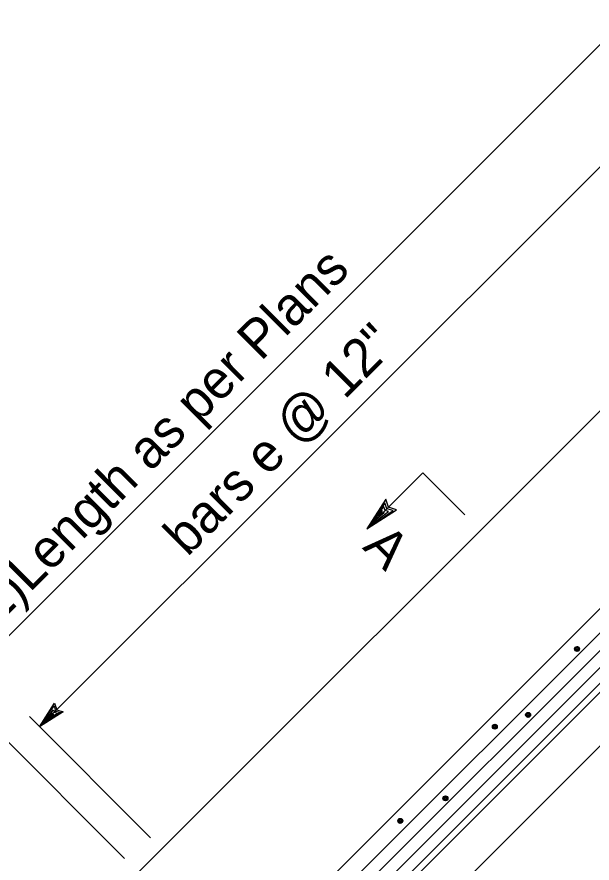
# Model space of a CAD drawing. Extents: x -0.08 to 2.83, y -0.03 to 1.92.
# Drawn here: x 0.22 to 0.4158, y 1.327 to 1.6151 of the extents above; entities that cross this region are included whole.
import ezdxf

# ---------------------------------------------------------------- set-up
doc = ezdxf.new("R2010")
doc.units = 0
for name, color, linetype in [('50', 7, 'Continuous'), ('51', 7, 'Continuous'), ('55', 7, 'Continuous'), ('57', 7, 'Continuous')]:
    doc.layers.add(name, color=color, linetype=linetype)

msp = doc.modelspace()

# ---------------------------------------------------------------- linework, layer by layer
at = {"layer": '50'}
for p, q in [((0.26143, 1.32383), (0.52603, 1.58845)), ((0.29508, 1.29018), (0.52603, 1.52115)), ((0.30931, 1.27596), (0.54531, 1.51199)), ((0.31847, 1.2668), (0.55291, 1.50128)), ((0.30513, 1.28013), (0.51959, 1.49462))]:
    msp.add_line(p, q, dxfattribs=at)
at = {"layer": '51'}
for p, q in [((0.5075, 1.49439), (0.30176, 1.28865)), ((0.51042, 1.4913), (0.30496, 1.28583))]:
    msp.add_line(p, q, dxfattribs=at)
for points in [[(0.41021, 1.40049), (0.41052, 1.40064), (0.41084, 1.40065), (0.41114, 1.40053), (0.41135, 1.40034), (0.41146, 1.40014), (0.41148, 1.39991), (0.41143, 1.39967), (0.41135, 1.39946), (0.41118, 1.39926), (0.41095, 1.39912), (0.41073, 1.39908), (0.41047, 1.39912), (0.41024, 1.39924), (0.41002, 1.39946), (0.40995, 1.39971), (0.40992, 1.39994), (0.40996, 1.40013), (0.41006, 1.40031), (0.41019, 1.40043), (0.41038, 1.40052), (0.41057, 1.40059), (0.4108, 1.4006), (0.41096, 1.40057), (0.4111, 1.40052), (0.41119, 1.40042), (0.41133, 1.40029), (0.41139, 1.40013), (0.41141, 1.39997), (0.41142, 1.39982), (0.41138, 1.39964), (0.41129, 1.39948), (0.41117, 1.39933), (0.41104, 1.39924), (0.41086, 1.39914), (0.41074, 1.39913), (0.41057, 1.39915), (0.41043, 1.39919), (0.41031, 1.39927), (0.41017, 1.39937), (0.41004, 1.39956), (0.40999, 1.39975), (0.40997, 1.39994), (0.41004, 1.40018), (0.41016, 1.40034), (0.41034, 1.40044), (0.41052, 1.40052), (0.41073, 1.40055), (0.41089, 1.40054), (0.41103, 1.40048), (0.41119, 1.40036), (0.41129, 1.40021), (0.41133, 1.40006), (0.41135, 1.39987), (0.41131, 1.39967), (0.41121, 1.3995), (0.41107, 1.39935), (0.41095, 1.39925), (0.41073, 1.39919), (0.41056, 1.39921), (0.4104, 1.39928), (0.41023, 1.39941), (0.41011, 1.39959), (0.41004, 1.39977), (0.41004, 1.39994), (0.41008, 1.40009), (0.41016, 1.40022), (0.41028, 1.40035), (0.41041, 1.4004), (0.41055, 1.40045), (0.41068, 1.40048), (0.41087, 1.40048), (0.41102, 1.40043), (0.41115, 1.40032), (0.41123, 1.40019), (0.41126, 1.39996), (0.41123, 1.39976), (0.41116, 1.39958), (0.41102, 1.39941), (0.4109, 1.39933), (0.4108, 1.39929), (0.41061, 1.39926), (0.4105, 1.3993), (0.41031, 1.3994), (0.41019, 1.39957), (0.41012, 1.39976), (0.4101, 1.39994), (0.41015, 1.40011), (0.41023, 1.40024), (0.41039, 1.40034), (0.41059, 1.40039), (0.41077, 1.40043), (0.41092, 1.40043), (0.41107, 1.40035), (0.4111, 1.40028), (0.41117, 1.40018), (0.41118, 1.40006), (0.41118, 1.39988), (0.41117, 1.39977), (0.41114, 1.39967), (0.4111, 1.39958)], [(0.4111, 1.39958), (0.41089, 1.39944), (0.41076, 1.39933), (0.41064, 1.39933), (0.4105, 1.39937), (0.41037, 1.39946), (0.41025, 1.39956), (0.41019, 1.39972), (0.41017, 1.39987), (0.41017, 1.4), (0.41022, 1.40013), (0.41039, 1.40026), (0.41056, 1.40032), (0.41071, 1.40035), (0.41088, 1.40038), (0.41102, 1.40032), (0.41108, 1.40016), (0.41109, 1.40008), (0.4111, 1.39994), (0.41109, 1.39983), (0.41106, 1.39972), (0.41101, 1.39963), (0.41095, 1.39955), (0.41087, 1.39951), (0.41074, 1.39943), (0.41066, 1.3994), (0.41061, 1.3994), (0.4105, 1.39942), (0.41045, 1.39946), (0.41039, 1.3995), (0.41032, 1.39957), (0.41029, 1.39962), (0.41024, 1.39969), (0.41023, 1.39978), (0.41026, 1.40002), (0.41031, 1.40011), (0.4104, 1.4002), (0.41052, 1.40025), (0.4106, 1.40027), (0.41071, 1.40031), (0.4108, 1.40031), (0.41089, 1.4003), (0.41097, 1.40026), (0.41103, 1.40013), (0.41104, 1.40009), (0.41104, 1.4), (0.41103, 1.39991), (0.41102, 1.39983), (0.41099, 1.39976), (0.41098, 1.3997), (0.41094, 1.39963), (0.41092, 1.3996), (0.41084, 1.39956), (0.4108, 1.39954), (0.41074, 1.39951), (0.41066, 1.39949), (0.41059, 1.39948), (0.41053, 1.39949), (0.41045, 1.39954), (0.41039, 1.3996), (0.41034, 1.39966), (0.41032, 1.39972), (0.41031, 1.39982), (0.41031, 1.39991), (0.41034, 1.39998), (0.41037, 1.40004), (0.41039, 1.40011), (0.41047, 1.40013), (0.41055, 1.40016), (0.41064, 1.4002), (0.41072, 1.40022), (0.4108, 1.40022), (0.41086, 1.4002), (0.41092, 1.40013), (0.41096, 1.40004), (0.41097, 1.4), (0.41095, 1.3999), (0.41094, 1.39983), (0.41093, 1.39979), (0.41091, 1.39974), (0.41087, 1.39969), (0.41082, 1.39963), (0.4108, 1.39961), (0.41076, 1.39959), (0.4107, 1.39958), (0.41065, 1.39958), (0.41062, 1.39958), (0.41059, 1.39957), (0.41055, 1.39957), (0.41051, 1.39959), (0.41047, 1.39963), (0.41043, 1.39968), (0.4104, 1.39972), (0.41038, 1.39977), (0.41037, 1.39984), (0.41037, 1.39989), (0.41038, 1.39994), (0.41042, 1.39998), (0.41044, 1.40004), (0.41047, 1.40008), (0.41053, 1.40009)], [(0.39353, 1.37802), (0.39384, 1.37818), (0.39416, 1.37818), (0.39446, 1.37807), (0.39466, 1.37788), (0.39478, 1.37768), (0.3948, 1.37744), (0.39477, 1.3772), (0.39467, 1.377), (0.3945, 1.3768), (0.39428, 1.37666), (0.39406, 1.37662), (0.39379, 1.37666), (0.39356, 1.37678), (0.39335, 1.37699), (0.39327, 1.37725), (0.39325, 1.37748), (0.39329, 1.37766), (0.39338, 1.37785), (0.39352, 1.37797), (0.3937, 1.37806), (0.3939, 1.37813), (0.39412, 1.37814), (0.39429, 1.3781), (0.39442, 1.37806), (0.39453, 1.37796), (0.39465, 1.37783), (0.39471, 1.37767), (0.39473, 1.37751), (0.39474, 1.37736), (0.39471, 1.37719), (0.39462, 1.37702), (0.39449, 1.37688), (0.39437, 1.37678), (0.39419, 1.37668), (0.39407, 1.37667), (0.39391, 1.3767), (0.39376, 1.37672), (0.39363, 1.3768), (0.39349, 1.37692), (0.39337, 1.37709), (0.39331, 1.3773), (0.3933, 1.37748), (0.39337, 1.37771), (0.39348, 1.37787), (0.39366, 1.37798), (0.39385, 1.37806), (0.39406, 1.37808), (0.39421, 1.37808), (0.39437, 1.37801), (0.39452, 1.3779), (0.39461, 1.37775), (0.39465, 1.3776), (0.39466, 1.37741), (0.39462, 1.3772), (0.39453, 1.37704), (0.3944, 1.37688), (0.39427, 1.37679), (0.39406, 1.37672), (0.39388, 1.37675), (0.39372, 1.37682), (0.39355, 1.37695), (0.39343, 1.37713), (0.39337, 1.37731), (0.39337, 1.37747), (0.3934, 1.37764), (0.39348, 1.37776), (0.3936, 1.37788), (0.39374, 1.37793), (0.39387, 1.37798), (0.39401, 1.37801), (0.3942, 1.37801), (0.39435, 1.37797), (0.39447, 1.37785), (0.39455, 1.37773), (0.39458, 1.37749), (0.39456, 1.3773), (0.39449, 1.37711), (0.39435, 1.37695), (0.39422, 1.37687), (0.39413, 1.37682), (0.39394, 1.3768), (0.39382, 1.37684), (0.39364, 1.37693), (0.39352, 1.37711), (0.39344, 1.3773), (0.39343, 1.37747), (0.39347, 1.37764), (0.39356, 1.37777), (0.39371, 1.37787), (0.39391, 1.37793), (0.39409, 1.37797), (0.39424, 1.37797), (0.39439, 1.37788), (0.39442, 1.37782), (0.39449, 1.37773), (0.39451, 1.3776), (0.39451, 1.37742), (0.39449, 1.37731), (0.39446, 1.37721), (0.39442, 1.37711)], [(0.39442, 1.37711), (0.39421, 1.37698), (0.39408, 1.37687), (0.39396, 1.37688), (0.39382, 1.3769), (0.3937, 1.37699), (0.39358, 1.3771), (0.39351, 1.37725), (0.39349, 1.3774), (0.39351, 1.37754), (0.39355, 1.37767), (0.39371, 1.37779), (0.39388, 1.37786), (0.39403, 1.37788), (0.3942, 1.37792), (0.39434, 1.37785), (0.3944, 1.37769), (0.39441, 1.37761), (0.39442, 1.37747), (0.39441, 1.37737), (0.39439, 1.37725), (0.39433, 1.37717), (0.39427, 1.37709), (0.3942, 1.37704), (0.39406, 1.37697), (0.39399, 1.37693), (0.39394, 1.37694), (0.39382, 1.37697), (0.39377, 1.37699), (0.39371, 1.37704), (0.39365, 1.37711), (0.39361, 1.37715), (0.39356, 1.37722), (0.39356, 1.37731), (0.39359, 1.37755), (0.39363, 1.37765), (0.39372, 1.37774), (0.39384, 1.37779), (0.39392, 1.37781), (0.39403, 1.37784), (0.39412, 1.37784), (0.39421, 1.37784), (0.3943, 1.3778), (0.39436, 1.37767), (0.39437, 1.37762), (0.39437, 1.37754), (0.39437, 1.37745), (0.39434, 1.37737), (0.39432, 1.3773), (0.3943, 1.37723), (0.39427, 1.37717), (0.39424, 1.37714), (0.39416, 1.3771), (0.39412, 1.37707), (0.39407, 1.37704), (0.39399, 1.37702), (0.39391, 1.37702), (0.39386, 1.37703), (0.39377, 1.37709), (0.39371, 1.37714), (0.39366, 1.3772), (0.39365, 1.37726), (0.39363, 1.37735), (0.39363, 1.37744), (0.39366, 1.37751), (0.39369, 1.37757), (0.39371, 1.37764), (0.39379, 1.37766), (0.39387, 1.37769), (0.39397, 1.37774), (0.39404, 1.37776), (0.39412, 1.37776), (0.39419, 1.37774), (0.39424, 1.37766), (0.39429, 1.37757), (0.39429, 1.37754), (0.39428, 1.37744), (0.39427, 1.37737), (0.39425, 1.37733), (0.39423, 1.37728), (0.3942, 1.37722), (0.39415, 1.37717), (0.39412, 1.37714), (0.39408, 1.37713), (0.39403, 1.37712), (0.39397, 1.37712), (0.39394, 1.37711), (0.39391, 1.37711), (0.39387, 1.37711), (0.39384, 1.37713), (0.3938, 1.37716), (0.39376, 1.37722), (0.39372, 1.37726), (0.39371, 1.37731), (0.3937, 1.37737), (0.39369, 1.37743), (0.3937, 1.37747), (0.39374, 1.37751), (0.39376, 1.37757), (0.39379, 1.37761), (0.39386, 1.37764)], [(0.38222, 1.37404), (0.38252, 1.37418), (0.38285, 1.37419), (0.38315, 1.37408), (0.38336, 1.37389), (0.38347, 1.37368), (0.3835, 1.37345), (0.38346, 1.3732), (0.38336, 1.37301), (0.38318, 1.3728), (0.38296, 1.37266), (0.38274, 1.37263), (0.38248, 1.37267), (0.38226, 1.37279), (0.38204, 1.373), (0.38195, 1.37326), (0.38194, 1.37348), (0.38198, 1.37367), (0.38207, 1.37386), (0.38221, 1.37398), (0.38239, 1.37407), (0.38258, 1.37413), (0.38281, 1.37415), (0.38297, 1.37411), (0.38311, 1.37406), (0.38321, 1.37397), (0.38334, 1.37384), (0.38341, 1.37368), (0.38343, 1.37352), (0.38343, 1.37337), (0.38339, 1.37319), (0.3833, 1.37303), (0.38318, 1.37288), (0.38305, 1.37279), (0.38288, 1.37269), (0.38275, 1.37267), (0.3826, 1.3727), (0.38246, 1.37273), (0.38232, 1.37281), (0.38218, 1.37292), (0.38206, 1.3731), (0.382, 1.3733), (0.38199, 1.37348), (0.38206, 1.37372), (0.38218, 1.37388), (0.38235, 1.37399), (0.38253, 1.37407), (0.38274, 1.37409), (0.3829, 1.37408), (0.38305, 1.37402), (0.38321, 1.37391), (0.3833, 1.37375), (0.38334, 1.37362), (0.38335, 1.37342), (0.38331, 1.37321), (0.38322, 1.37305), (0.38308, 1.3729), (0.38296, 1.37279), (0.38274, 1.37273), (0.38256, 1.37276), (0.38242, 1.37282), (0.38225, 1.37295), (0.38211, 1.37314), (0.38205, 1.37332), (0.38205, 1.37348), (0.38209, 1.37364), (0.38216, 1.37377), (0.38229, 1.37389), (0.38242, 1.37395), (0.38256, 1.37399), (0.3827, 1.37402), (0.38288, 1.37402), (0.38304, 1.37397), (0.38316, 1.37386), (0.38324, 1.37374), (0.38327, 1.3735), (0.38325, 1.37331), (0.38318, 1.37311), (0.38304, 1.37296), (0.38291, 1.37288), (0.38282, 1.37282), (0.38263, 1.3728), (0.38251, 1.37285), (0.38232, 1.37294), (0.38221, 1.3731), (0.38213, 1.37331), (0.38211, 1.37348), (0.38216, 1.37365), (0.38225, 1.37379), (0.3824, 1.37387), (0.3826, 1.37394), (0.38277, 1.37397), (0.38293, 1.37397), (0.38308, 1.37389), (0.38312, 1.37383), (0.38318, 1.37373), (0.3832, 1.37362), (0.3832, 1.37342), (0.38318, 1.37332), (0.38315, 1.37321), (0.3831, 1.37312)], [(0.3831, 1.37312), (0.3829, 1.37298), (0.38276, 1.37288), (0.38265, 1.37288), (0.38251, 1.37291), (0.38238, 1.37299), (0.38226, 1.3731), (0.3822, 1.37326), (0.38218, 1.37341), (0.38219, 1.37355), (0.38224, 1.37368), (0.3824, 1.3738), (0.38256, 1.37387), (0.38272, 1.37389), (0.38288, 1.37392), (0.38303, 1.37386), (0.38309, 1.3737), (0.3831, 1.37362), (0.38312, 1.37348), (0.3831, 1.37337), (0.38307, 1.37326), (0.38303, 1.37318), (0.38296, 1.3731), (0.38288, 1.37305), (0.38275, 1.37298), (0.38268, 1.37294), (0.38263, 1.37295), (0.38251, 1.37297), (0.38246, 1.373), (0.3824, 1.37305), (0.38234, 1.3731), (0.3823, 1.37316), (0.38226, 1.37323), (0.38225, 1.37332), (0.38227, 1.37356), (0.38232, 1.37366), (0.38242, 1.37374), (0.38252, 1.37379), (0.38261, 1.37383), (0.38272, 1.37385), (0.38281, 1.37385), (0.3829, 1.37384), (0.38298, 1.37381), (0.38305, 1.37368), (0.38305, 1.37363), (0.38305, 1.37354), (0.38305, 1.37345), (0.38304, 1.37337), (0.38301, 1.37331), (0.38299, 1.37325), (0.38296, 1.37318), (0.38293, 1.37314), (0.38285, 1.3731), (0.38281, 1.37308), (0.38275, 1.37306), (0.38268, 1.37303), (0.3826, 1.37303), (0.38254, 1.37304), (0.38246, 1.3731), (0.3824, 1.37314), (0.38235, 1.37319), (0.38233, 1.37327), (0.38232, 1.37336), (0.38232, 1.37345), (0.38235, 1.37352), (0.38238, 1.37358), (0.3824, 1.37365), (0.38248, 1.37367), (0.38255, 1.3737), (0.38266, 1.37374), (0.38272, 1.37376), (0.3828, 1.37377), (0.38288, 1.37374), (0.38293, 1.37367), (0.38297, 1.37358), (0.38297, 1.37354), (0.38297, 1.37344), (0.38295, 1.37337), (0.38293, 1.37334), (0.38292, 1.37328), (0.38288, 1.37323), (0.38284, 1.37318), (0.3828, 1.37315), (0.38277, 1.37313), (0.38271, 1.37313), (0.38267, 1.37313), (0.38263, 1.37312), (0.3826, 1.3731), (0.38256, 1.3731), (0.38252, 1.37313), (0.38248, 1.37317), (0.38246, 1.37323), (0.38242, 1.37327), (0.38239, 1.37332), (0.38239, 1.37337), (0.38238, 1.37344), (0.38239, 1.37348), (0.38243, 1.37352), (0.38246, 1.37358), (0.38248, 1.37362), (0.38254, 1.37364)], [(0.36539, 1.34962), (0.3657, 1.34978), (0.36602, 1.34979), (0.36632, 1.34967), (0.36653, 1.34947), (0.36663, 1.34927), (0.36667, 1.34904), (0.36663, 1.3488), (0.36654, 1.3486), (0.36636, 1.34839), (0.36614, 1.34826), (0.36592, 1.34822), (0.36565, 1.34826), (0.36543, 1.34837), (0.36521, 1.34858), (0.36513, 1.34885), (0.3651, 1.34908), (0.36515, 1.34927), (0.36525, 1.34944), (0.36538, 1.34958), (0.36556, 1.34966), (0.36575, 1.34972), (0.36599, 1.34973), (0.36615, 1.34971), (0.36628, 1.34965), (0.36638, 1.34955), (0.36651, 1.34943), (0.36658, 1.34927), (0.3666, 1.34911), (0.3666, 1.34896), (0.36656, 1.34879), (0.36648, 1.34862), (0.36636, 1.34848), (0.36623, 1.34837), (0.36604, 1.34828), (0.36592, 1.34827), (0.36576, 1.34829), (0.36562, 1.34832), (0.36549, 1.3484), (0.36535, 1.3485), (0.36523, 1.3487), (0.36517, 1.34889), (0.36516, 1.34908), (0.36523, 1.34931), (0.36535, 1.34947), (0.36551, 1.34958), (0.3657, 1.34966), (0.36592, 1.34968), (0.36607, 1.34968), (0.36622, 1.34962), (0.36637, 1.3495), (0.36647, 1.34934), (0.36651, 1.3492), (0.36652, 1.349), (0.36648, 1.3488), (0.36639, 1.34864), (0.36625, 1.34849), (0.36612, 1.34839), (0.36592, 1.34832), (0.36574, 1.34835), (0.36559, 1.34841), (0.36541, 1.34854), (0.36529, 1.34873), (0.36522, 1.3489), (0.36522, 1.34906), (0.36526, 1.34923), (0.36534, 1.34936), (0.36546, 1.34948), (0.3656, 1.34953), (0.36574, 1.34959), (0.36586, 1.3496), (0.36606, 1.34962), (0.3662, 1.34957), (0.36633, 1.34946), (0.36641, 1.34933), (0.36644, 1.3491), (0.36642, 1.3489), (0.36635, 1.34871), (0.3662, 1.34855), (0.36608, 1.34848), (0.36599, 1.34842), (0.3658, 1.34839), (0.36569, 1.34844), (0.36549, 1.34853), (0.36538, 1.3487), (0.3653, 1.3489), (0.36529, 1.34906), (0.36534, 1.34924), (0.36541, 1.34937), (0.36557, 1.34947), (0.36578, 1.34952), (0.36595, 1.34956), (0.36611, 1.34957), (0.36624, 1.34948), (0.36629, 1.34942), (0.36636, 1.34932), (0.36637, 1.3492), (0.36637, 1.34901), (0.36636, 1.34891), (0.36632, 1.3488), (0.36627, 1.34872)], [(0.36627, 1.34872), (0.36607, 1.34858), (0.36594, 1.34848), (0.36582, 1.34848), (0.36567, 1.3485), (0.36555, 1.34858), (0.36543, 1.3487), (0.36536, 1.34885), (0.36535, 1.349), (0.36536, 1.34913), (0.36541, 1.34927), (0.36557, 1.34939), (0.36574, 1.34946), (0.36589, 1.34949), (0.36607, 1.34952), (0.3662, 1.34946), (0.36626, 1.3493), (0.36627, 1.34921), (0.36629, 1.34907), (0.36627, 1.34896), (0.36624, 1.34885), (0.3662, 1.34877), (0.36612, 1.34869), (0.36605, 1.34864), (0.36592, 1.34857), (0.36585, 1.34853), (0.3658, 1.34853), (0.36569, 1.34856), (0.36562, 1.34858), (0.36557, 1.34864), (0.36551, 1.3487), (0.36547, 1.34875), (0.36543, 1.34882), (0.36541, 1.34892), (0.36544, 1.34915), (0.36549, 1.34925), (0.36559, 1.34934), (0.3657, 1.34939), (0.36578, 1.34942), (0.36589, 1.34944), (0.36598, 1.34944), (0.36608, 1.34943), (0.36615, 1.34939), (0.36621, 1.34927), (0.36623, 1.34922), (0.36623, 1.34913), (0.36622, 1.34905), (0.3662, 1.34896), (0.36617, 1.3489), (0.36616, 1.34884), (0.36612, 1.34877), (0.3661, 1.34873), (0.36602, 1.3487), (0.36599, 1.34868), (0.36592, 1.34865), (0.36585, 1.34863), (0.36578, 1.34862), (0.36571, 1.34864), (0.36562, 1.34868), (0.36557, 1.34873), (0.36553, 1.34879), (0.3655, 1.34886), (0.36549, 1.34895), (0.36549, 1.34904), (0.36551, 1.34911), (0.36554, 1.34918), (0.36557, 1.34924), (0.36565, 1.34926), (0.36572, 1.3493), (0.36582, 1.34934), (0.3659, 1.34935), (0.36597, 1.34936), (0.36604, 1.34934), (0.36611, 1.34927), (0.36615, 1.34918), (0.36615, 1.34913), (0.36614, 1.34903), (0.36612, 1.34896), (0.36611, 1.34892), (0.36608, 1.34888), (0.36605, 1.34882), (0.36601, 1.34877), (0.36597, 1.34874), (0.36595, 1.34872), (0.36588, 1.34872), (0.36583, 1.34872), (0.36581, 1.34872), (0.36578, 1.3487), (0.36574, 1.3487), (0.36569, 1.34873), (0.36565, 1.34876), (0.36562, 1.34882), (0.36559, 1.34886), (0.36557, 1.34891), (0.36556, 1.34897), (0.36554, 1.34903), (0.36556, 1.34906), (0.3656, 1.34912), (0.36562, 1.34917), (0.36565, 1.34921), (0.36571, 1.34923)], [(0.35003, 1.34194), (0.35033, 1.34209), (0.35066, 1.34209), (0.35096, 1.34198), (0.35117, 1.34179), (0.35127, 1.34158), (0.3513, 1.34135), (0.35126, 1.3411), (0.35117, 1.3409), (0.351, 1.3407), (0.35077, 1.34056), (0.35055, 1.34053), (0.35029, 1.34057), (0.35006, 1.34069), (0.34984, 1.3409), (0.34976, 1.34116), (0.34974, 1.34139), (0.34978, 1.34158), (0.34988, 1.34176), (0.35001, 1.34188), (0.3502, 1.34197), (0.35039, 1.34203), (0.35062, 1.34204), (0.35078, 1.34201), (0.35091, 1.34196), (0.35101, 1.34187), (0.35115, 1.34174), (0.35121, 1.34158), (0.35123, 1.34142), (0.35123, 1.34127), (0.3512, 1.34109), (0.35111, 1.34093), (0.35099, 1.34078), (0.35086, 1.34069), (0.35068, 1.34059), (0.35056, 1.34057), (0.35039, 1.3406), (0.35025, 1.34063), (0.35012, 1.34072), (0.34998, 1.34081), (0.34987, 1.341), (0.34981, 1.3412), (0.34979, 1.34139), (0.34987, 1.34162), (0.34998, 1.34179), (0.35015, 1.34188), (0.35034, 1.34196), (0.35055, 1.342), (0.3507, 1.34199), (0.35086, 1.34193), (0.35101, 1.34181), (0.35111, 1.34165), (0.35114, 1.34151), (0.35115, 1.34132), (0.35113, 1.34111), (0.35102, 1.34095), (0.35089, 1.34079), (0.35077, 1.34069), (0.35055, 1.34063), (0.35038, 1.34066), (0.35022, 1.34073), (0.35005, 1.34085), (0.34992, 1.34104), (0.34986, 1.34121), (0.34986, 1.34138), (0.3499, 1.34154), (0.34997, 1.34166), (0.3501, 1.34179), (0.35023, 1.34184), (0.35037, 1.34189), (0.3505, 1.34192), (0.35069, 1.34193), (0.35085, 1.34187), (0.35097, 1.34176), (0.35104, 1.34164), (0.35108, 1.3414), (0.35105, 1.34121), (0.35098, 1.34101), (0.35085, 1.34086), (0.35072, 1.34077), (0.35062, 1.34073), (0.35043, 1.3407), (0.35032, 1.34075), (0.35014, 1.34084), (0.35001, 1.34101), (0.34994, 1.34121), (0.34992, 1.34138), (0.34996, 1.34155), (0.35005, 1.34169), (0.3502, 1.34179), (0.35041, 1.34184), (0.35059, 1.34187), (0.35074, 1.34187), (0.35088, 1.34179), (0.35092, 1.34173), (0.35099, 1.34163), (0.351, 1.34151), (0.351, 1.34133), (0.35099, 1.34122), (0.35096, 1.34111), (0.35091, 1.34102)], [(0.35091, 1.34102), (0.3507, 1.34089), (0.35057, 1.34077), (0.35046, 1.34078), (0.3503, 1.34081), (0.35018, 1.34089), (0.35007, 1.34101), (0.35, 1.34116), (0.34998, 1.34131), (0.35, 1.34145), (0.35004, 1.34158), (0.3502, 1.3417), (0.35038, 1.34176), (0.35053, 1.34179), (0.3507, 1.34183), (0.35083, 1.34176), (0.35089, 1.34161), (0.35091, 1.34153), (0.35092, 1.34139), (0.35091, 1.34128), (0.35088, 1.34116), (0.35083, 1.34108), (0.35077, 1.341), (0.35069, 1.34095), (0.35055, 1.34087), (0.35048, 1.34084), (0.35043, 1.34085), (0.35032, 1.34087), (0.35026, 1.3409), (0.3502, 1.34095), (0.35015, 1.34101), (0.3501, 1.34106), (0.35006, 1.34113), (0.35005, 1.34123), (0.35008, 1.34145), (0.35013, 1.34156), (0.35022, 1.34165), (0.35033, 1.3417), (0.35041, 1.34172), (0.35053, 1.34175), (0.35061, 1.34175), (0.35071, 1.34175), (0.35079, 1.34171), (0.35085, 1.34158), (0.35086, 1.34153), (0.35086, 1.34145), (0.35086, 1.34136), (0.35084, 1.34128), (0.35081, 1.34121), (0.3508, 1.34115), (0.35076, 1.34108), (0.35073, 1.34105), (0.35066, 1.34101), (0.35062, 1.34098), (0.35056, 1.34095), (0.35048, 1.34094), (0.35041, 1.34093), (0.35034, 1.34094), (0.35026, 1.34099), (0.35021, 1.34105), (0.35016, 1.3411), (0.35014, 1.34117), (0.35012, 1.34126), (0.35013, 1.34135), (0.35015, 1.34142), (0.35018, 1.34149), (0.35021, 1.34155), (0.35029, 1.34158), (0.35037, 1.34161), (0.35046, 1.34165), (0.35054, 1.34166), (0.3506, 1.34166), (0.35068, 1.34165), (0.35074, 1.34158), (0.35078, 1.34149), (0.35078, 1.34145), (0.35078, 1.34134), (0.35075, 1.34128), (0.35075, 1.34124), (0.35072, 1.34118), (0.35069, 1.34113), (0.35065, 1.34108), (0.3506, 1.34106), (0.35058, 1.34103), (0.35052, 1.34102), (0.35047, 1.34102), (0.35044, 1.34102), (0.35041, 1.34101), (0.35037, 1.34101), (0.35033, 1.34103), (0.35029, 1.34107), (0.35025, 1.34113), (0.35022, 1.34117), (0.3502, 1.34122), (0.35019, 1.34128), (0.35018, 1.34134), (0.3502, 1.34138), (0.35023, 1.34142), (0.35026, 1.34149), (0.35029, 1.34153), (0.35034, 1.34154)]]:
    msp.add_lwpolyline(points, dxfattribs=at)
for centre in [(0.41071, 1.39987), (0.39404, 1.37741), (0.38273, 1.37342), (0.3659, 1.34901), (0.35053, 1.34132)]:
    msp.add_circle(centre, 0.00084, dxfattribs=at)
at = {"layer": '55'}
for p, q in [((0.19906, 1.3862), (0.42794, 1.6151)), ((0.22776, 1.37332), (0.43804, 1.58362)), ((0.30777, 1.27749), (0.52223, 1.49198)), ((0.2567, 1.32856), (0.19509, 1.39016)), ((0.22776, 1.37332), (0.23285, 1.38136)), ((0.22776, 1.37332), (0.23271, 1.38045)), ((0.23271, 1.38045), (0.23318, 1.37874)), ((0.23285, 1.38136), (0.23361, 1.37917)), ((0.2358, 1.37841), (0.22776, 1.37332)), ((0.22862, 1.37418), (0.23242, 1.37912)), ((0.23485, 1.37821), (0.22862, 1.37418)), ((0.22995, 1.37532), (0.23214, 1.37807)), ((0.23385, 1.37789), (0.22995, 1.37532)), ((0.23271, 1.3775), (0.23114, 1.37651)), ((0.23214, 1.37807), (0.2319, 1.37736)), ((0.2319, 1.37736), (0.23271, 1.3775)), ((0.23242, 1.37912), (0.23276, 1.37831)), ((0.23276, 1.37831), (0.23385, 1.37789)), ((0.23318, 1.37874), (0.23485, 1.37821)), ((0.23361, 1.37917), (0.2358, 1.37841)), ((0.26555, 1.33554), (0.22427, 1.37682)), ((0.23114, 1.37651), (0.23176, 1.37713))]:
    msp.add_line(p, q, dxfattribs=at)
at = {"layer": '57'}
for p, q in [((0.35817, 1.45981), (0.33918, 1.44081)), ((0.37247, 1.44551), (0.35817, 1.45981)), ((0.34556, 1.45085), (0.33918, 1.44081)), ((0.34527, 1.44965), (0.34025, 1.44189)), ((0.34596, 1.44759), (0.34527, 1.44965)), ((0.34647, 1.44811), (0.34556, 1.45085)), ((0.33918, 1.44081), (0.3492, 1.4472)), ((0.33918, 1.44081), (0.34807, 1.44697)), ((0.34025, 1.44189), (0.34647, 1.44663)), ((0.34487, 1.44845), (0.34168, 1.44355)), ((0.34442, 1.44697), (0.34316, 1.44503)), ((0.34425, 1.446), (0.34442, 1.44697)), ((0.34539, 1.44703), (0.34487, 1.44845)), ((0.34647, 1.44663), (0.34539, 1.44703)), ((0.34807, 1.44697), (0.34596, 1.44759)), ((0.3492, 1.4472), (0.34647, 1.44811)), ((0.34168, 1.44355), (0.3451, 1.44629)), ((0.34316, 1.44503), (0.3439, 1.44577)), ((0.3451, 1.44629), (0.34425, 1.446))]:
    msp.add_line(p, q, dxfattribs=at)

# ---------------------------------------------------------------- texts
for s, height, rotation, p in [('(L)Length as per Plans', 0.0130208, 45.0034, (0.20932, 1.40387)), ('bars e @ 12"', 0.0130208, 45.0033, (0.27804, 1.43102)), ('A', 0.01302, 315, (0.33734, 1.43419))]:
    msp.add_text(s, height=height, rotation=rotation, dxfattribs=at).set_placement(p)

doc.saveas('drawing.dxf')
